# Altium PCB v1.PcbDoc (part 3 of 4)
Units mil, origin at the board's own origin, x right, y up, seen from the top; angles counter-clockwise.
Board outline 3043 x 5109 mil, 2 copper layers (Top Layer, Bottom Layer), stack 62 mil thick; 379 components, 219 nets, 963 pads, 1099 vias.
Unrouted connection lines stored in the file: 1.
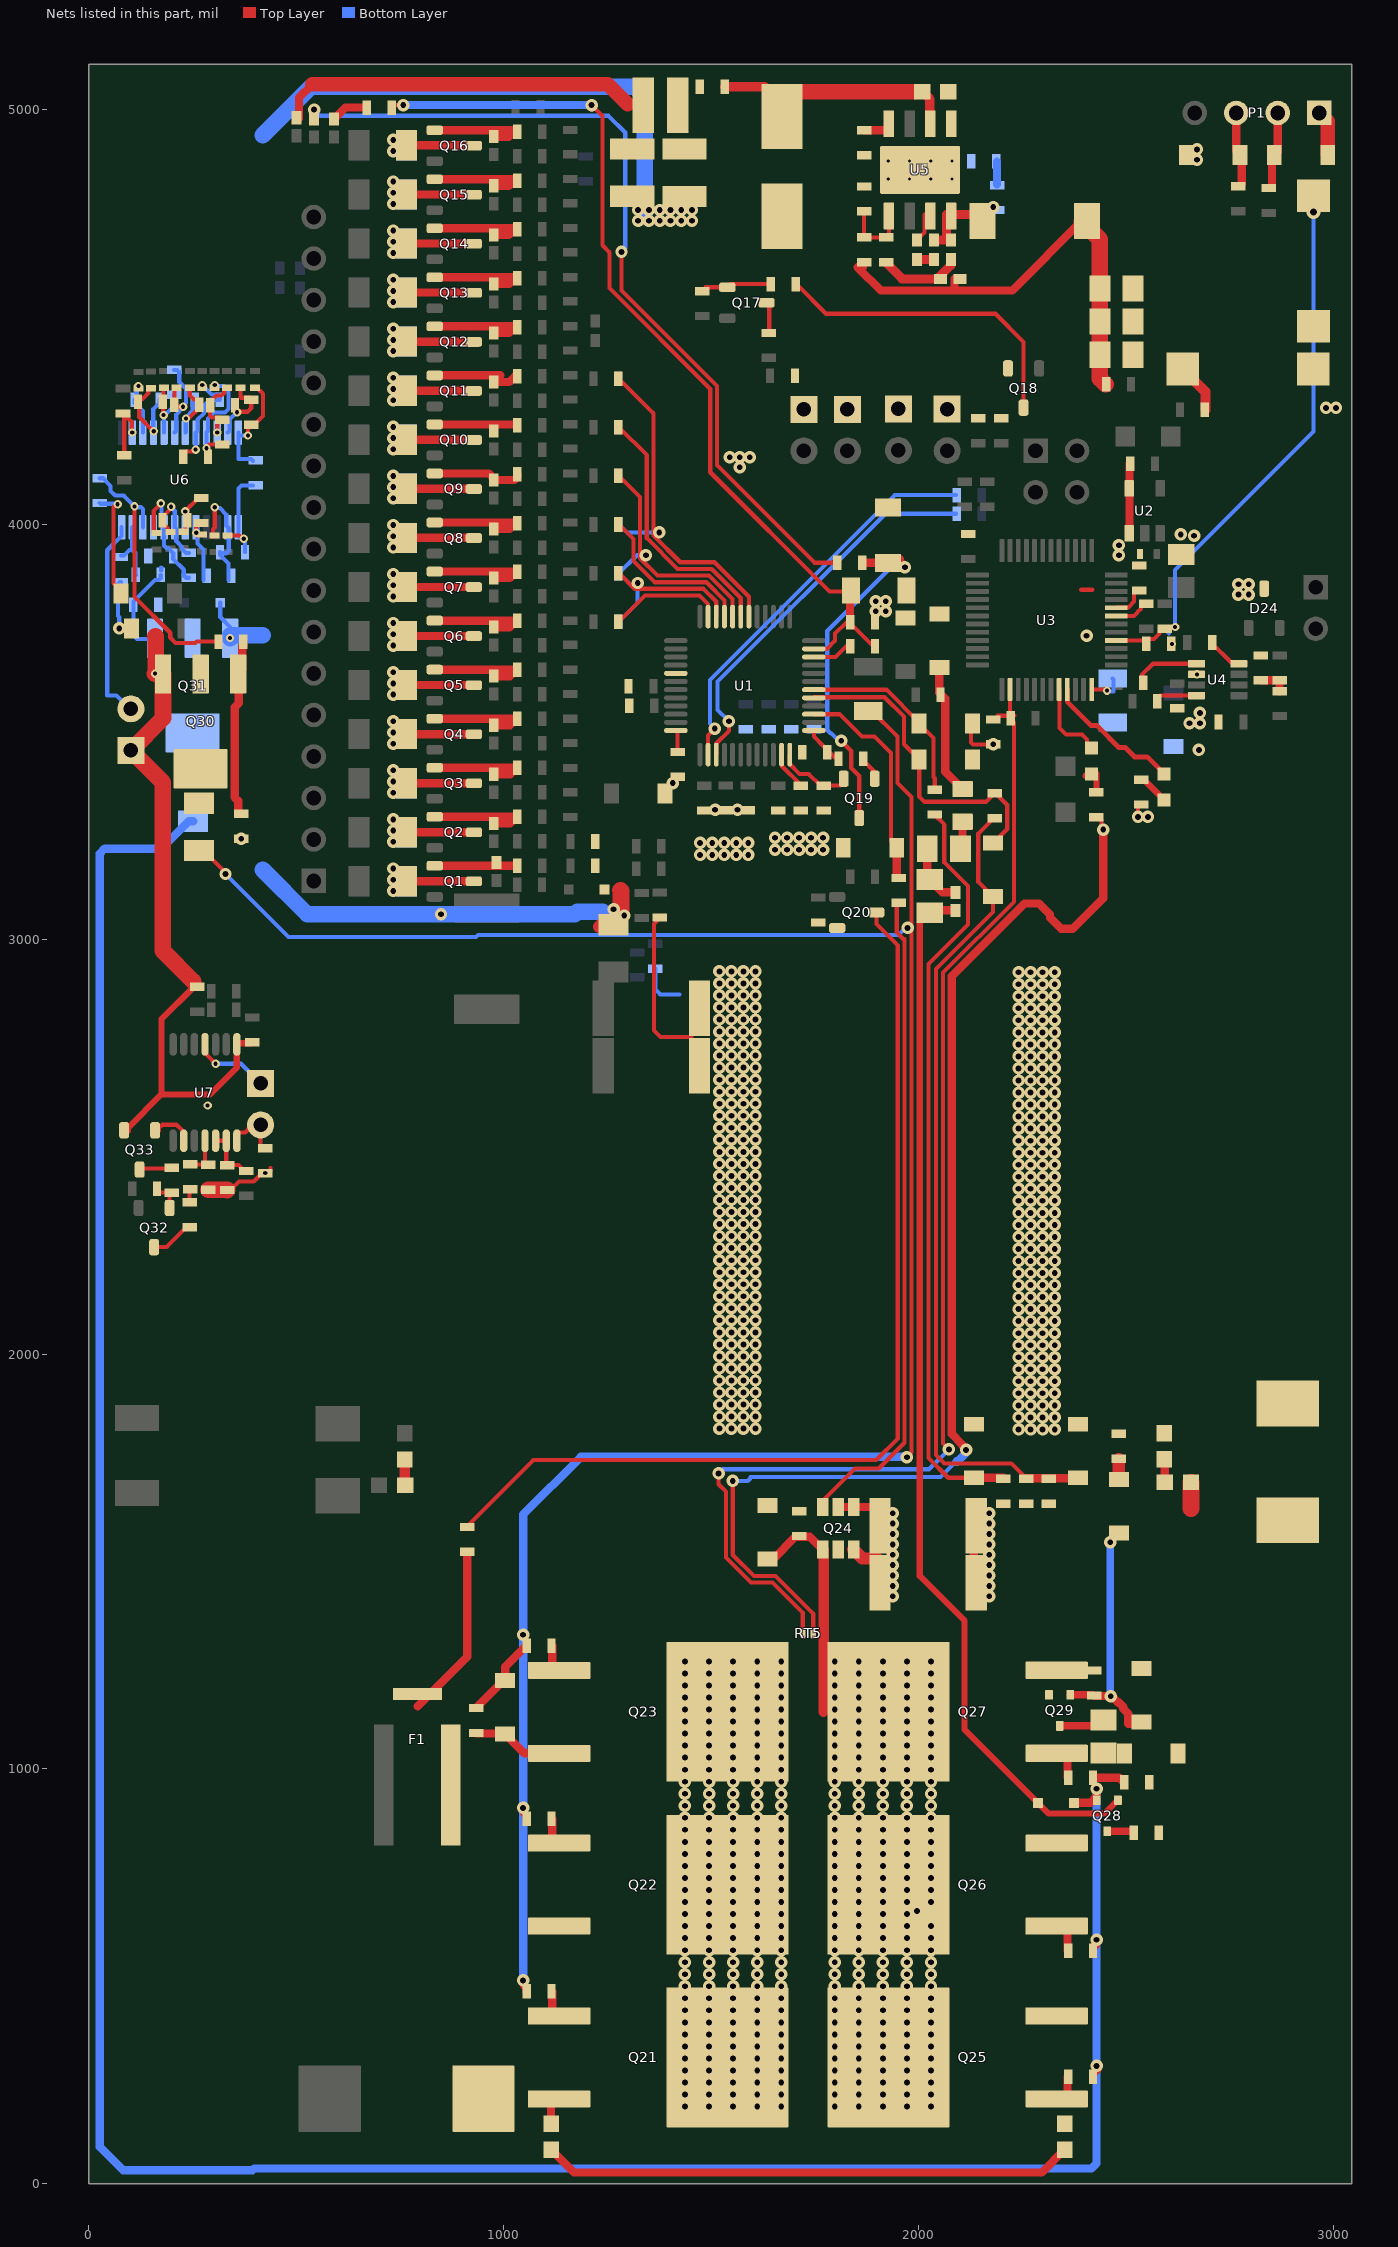
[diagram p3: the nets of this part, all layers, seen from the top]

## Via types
v1: diameter 30, hole 14, Top Layer to Bottom Layer, 1049 vias
v2: diameter 20, hole 10, Top Layer to Bottom Layer, 38 vias
v3: diameter 19.68, hole 7.87, Top Layer to Bottom Layer, tented both sides, 4 vias
v4: diameter 19.68, hole 7.87, Top Layer to Bottom Layer, 4 vias
v5: diameter 34, hole 16, Top Layer to Bottom Layer, 3 vias
v6: diameter 26, hole 10, Top Layer to Bottom Layer, 1 vias

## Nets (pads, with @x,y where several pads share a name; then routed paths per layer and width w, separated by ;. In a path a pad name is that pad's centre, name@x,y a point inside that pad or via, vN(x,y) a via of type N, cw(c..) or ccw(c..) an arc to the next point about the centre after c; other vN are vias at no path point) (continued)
GND: C1.2 C9.2 C15.1 C16.1 C17.2 C19.2 C23.2 C24.2 C25.2 C26.2 C27.1 C28.1 C30.2 C31.2 C32.2 C34.2 C35.2 C36.2 C37.1 C38.2 C39.2 C40.2 C41.1 C42.2 C43.1 C44.2 C45.2 C46.1 C47.2 C48.2 C49.2 C50.2 C51.2 C55.2 C56.2 C57.2 C64.2 C81.1 C82.1 C85.2 C86.2 C87.2 D9.2 D10.2 D21.2 D22.2 D23.2 D24.3 D32.2 D34.2 D35.2 D39.2 D41.2 D47.2 P1.1 Q18.2 Q20.2 Q30.3 Q31.3 Q33.2 R85.1 R91.1 R92.1 R99.1 R109.1 R110.1 R111.1 R116.1 R120.1 R171.1 R173.2 R174.1 R175.1 R177.2 RT1.1 RT2.1 RT3.1 RT4.1 RT5.1 RT6.1 S1.2 S2.2 U1.17 U2.1 U2.5 U3.7 U4.2 U5.1 U5.9@2003,4854 U6.21 U7.8 | length 7666.5
  Top Layer w10: C86.2@333.59,2395.35 341.09,2395.35 361.41,2415.68 397.18,2415.68 417.5,2436 v2(425,2436) 432.5,2436 437.5,2441 437.5,2448.5 ; v1(1551.41,1694.35) 1551.41,1516.35 1602.41,1465.35 1654.41,1465.35 1745.72,1374.03 RT5.1@1745.72,1326.85 ; D41.2@2129.88,3519.35 2126,3515.47 2126,3474 2130.46,3469.54 v1(2179.25,3469.54) ; 2391.55,3842.03 2418.09,3842.03 ; R109.1@2428,3294 2435.5,3294 2440.5,3289 v1@2440.5,3273.39 ; U3.7@2475.95,3779.02 2518.51,3779.02 2535.91,3796.42 2535.91,3803.35 2540.91,3808.35 C43.1@2548.41,3808.35 ; v1(2528.23,3294.56) 2528.23,3319.54 2533.23,3324.54 R110.1@2535.77,3324.54
  Top Layer w15: Q33.2@94.19,2537.6 94.19,2545.47 174.54,2625.83 ; C81.1@253.09,2885.35 174.54,2806.81 174.54,2625.83 ; C82.1@401.09,2751.35 C82.1@393.59,2751.35 391.16,2748.92 357.61,2748.92 356.36,2747.67 U7.8@356.36,2746.49 356.36,2690.36 291.83,2625.83 174.54,2625.83
  Top Layer w20: v1@2113,1770 2113,1772.71 2103.41,1782.3 2103.41,1783.19 2079.41,1807.19 2079.41,2910.65 2254.76,3086 2290,3086 2316.28,3059.72 2316.28,3051.63 2342.57,3025.35 2371.35,3025.35 2444.46,3098.46 v1(2444.46,3264.02) ; U2.1@2507.91,3979.12 C42.2@2507.91,4146.35
  Top Layer w30: R111.1@1229.91,3030.35 R111.1@1236.41,3036.84
  Top Layer w35: P1.1@2965.11,4991.3 2985.58,4970.83 D22.2@2985.58,4890.3
  Top Layer w40: v2(159,3640) 177.62,3640 Q30.3@178.45,3639.17 178.45,3532.45 RT6.1@101,3455 178.04,3377.96 178.04,2971.62 251,2898.66 ; 160.05,3730.48 161.09,3729.43 Q30.3@161.09,3650.37 ; R171.1@287.59,2396.35 332.59,2396.35 C86.2@333.59,2395.35 ; 1281,3118 1282.35,3116.65 1282.35,3071.06
  Bottom Layer w10: D47.2@316.31,3811 316.31,3776.66 340.24,3752.73 Q31.3@340.24,3731.69 ; v1(1551.41,1694.35) 1587.65,1694.35 1594,1700.69 1594,1703.35 2052.41,1703.35 2090.91,1741.85 ; 2592.41,3748.35 2596.69,3744.06 2596.69,3743.41 2602.84,3737.26
  Bottom Layer w20: 2090.91,1741.85 2094,1741.85 2114,1761.85 v1(2114,1769) v1@2113,1770
  Bottom Layer w40: Q31.3@340.24,3725.17 340.24,3731.69 340.55,3732 419,3732 ; 419,3166.93 525.93,3060 1170.77,3060 1177.11,3066.35 1238.41,3066.35 ; 419,4937.94 535.41,5054.35 1316.41,5054.35 1339.41,5031.35 v1@1339.41,4749.35
  other v1: 1290,3057 848.35,3060 1264.23,3072.27 1473,3203 1502,3203 1531,3203 1560,3203 1589,3203 1653.41,3215.35 1682.41,3215.35 1711.41,3215.35 1740.41,3215.35 1769.41,3215.35 1473,3232 1502,3232 1531,3232 1560,3232 1589,3232 367,3242 1653.41,3244.35 1682.41,3244.35 1711.41,3244.35 1740.41,3244.35 1769.41,3244.35 2552.23,3294.56 1509,3312 1563,3312 1407,3376 2675,3456 2652.41,3520.35 2677.41,3520.35 2677.41,3545.35 2404.41,3731.35 1896.41,3790.35 1920.41,3790.35 1896.41,3814.35 1920.41,3814.35 2770.41,3830.35 2795.41,3830.35 2770.41,3855.35 2795.41,3855.35 2482.41,3925.35 2482.41,3949.35 2663.41,3972.35 2631.41,3975.35 1568.41,4137.35 1544.41,4161.35 1568.41,4161.35 1592.41,4161.35 2981.41,4280.35 3005.41,4280.35 1323.41,4731.35 1349.41,4731.35 1375.41,4731.35 1401.41,4731.35 1427.41,4731.35 1453.41,4731.35 1323.41,4757.35 1349.41,4757.35 1375.41,4757.35 1401.41,4757.35 1427.41,4757.35 1453.41,4757.35 2670.41,4878.35 2670.41,4903.35
  other v2: 286,2599 2670.58,3638.14 2609.84,3711.42 339.82,3725.59
  other v3: 1926.23,4832.35 2079.77,4832.35 1926.23,4875.65 2079.77,4875.65
  other v4: 1977.41,4832.35 2028.59,4832.35 1977.41,4875.65 2028.59,4875.65
LD: D39.1 D42.2 R139.1 U1.41 | length 789.7
  Top Layer w10: U1.41@1747.09,3581.55 1747.09,3582.85 1917.91,3582.85 1964.62,3536.13 1964.62,3469.67 D39.1@2000.94,3433.35 2000.94,3343.81 2013.72,3331.03 2161.6,3331.03 2183.41,3352.84 2213.11,3323.14 2213.11,3265.61 D42.2@2179.32,3231.81
LED1: D25.2 U3.44 | length 195.4
  Top Layer w10: U3.44@2338.15,3601.85 2339.06,3600.95 2339.06,3508.7 2354.91,3492.84 2393.41,3492.84 2404.93,3481.32 2404.93,3471.86 D25.2@2415.68,3461.12
LED2: D26.2 U3.45 | length 335.2
  Top Layer w12: U3.45@2357.84,3601.85 2357.93,3601.76 2357.93,3572.15 2415.49,3514.59 2429.69,3514.59 2482.21,3462.07 2497.14,3462.07 2519.87,3439.35 2550.4,3439.35 D26.2@2591.41,3398.34
NetC15_2: C15.2 C16.2 C18.2 R61.2 U1.47 | length 2214.9
  Top Layer w10: R61.2@729.41,5004.35 729.41,5005.35 734.41,5010.35 v1(757.41,5010.35) ; v1(1211.41,5010.35) 1237.41,4984.35 1237.41,4672.35 1254.41,4655.35 1254.41,4569.35 1497.41,4326.35 1497.41,4125.35 1784.98,3837.78 C15.2@1833.91,3837.78 ; U1.47@1747.09,3699.66 1778.72,3699.66 1798.41,3719.35 1798.41,3736.35 1825.41,3763.35 1832.91,3763.35 C18.2@1889.91,3706.35 ; C16.2@1833.91,3774.35 C16.2@1836.41,3774.35
  Top Layer w20: C16.2@1833.91,3774.35 C15.2@1833.91,3837.78
  Bottom Layer w20: v1(757.41,5010.35) 1206.41,5010.35 v1@1211.41,5005.35
NetC18_1: C18.1 U1.46 | length 89.2
  Top Layer w10: U1.46@1747.09,3679.98 1799.04,3679.98 C18.1@1825.41,3706.35
NetC19_1: C19.1 U1.24 | length 52
  Top Layer w10: U1.24@1414.41,3502.81 1418.75,3498.47 C19.1@1418.75,3452.57
NetC31_1: C31.1 U1.35 | length 92.5
  Top Layer w10: U1.35@1669.33,3444.74 1669.33,3417.88 1715.64,3371.57 C31.1@1715.75,3371.57
NetC34_1: C34.1 Q19.2 U1.36 | length 185.3
  Top Layer w10: U1.36@1689.02,3444.74 1689.02,3422.1 1712.7,3398.42 1734.57,3398.42 1762.91,3370.08 C34.1@1770.41,3370.08 1809.88,3370.08 1819.01,3379.21 Q19.2@1819.01,3386.59
NetC36_1: C36.1 Q19.3 R96.1 | length 856
  Top Layer w10: v1(1813,3478) 1837.22,3453.78 1837.22,3412.09 1856.41,3392.9 Q19.3@1856.41,3292.1
  Top Layer w20: R96.1@1864.91,3907.35 1924.48,3907.35 C36.1@1925.41,3906.42 1935.12,3916.13 1954.69,3916.13 1954.69,3910.77 1966.41,3899.05 v1(1966.41,3896.35)
  Bottom Layer w10: v1(1813,3478) 1807.59,3478 1789.62,3495.97 1787.79,3495.97 1779.41,3504.35 1779.41,3742.35 1933.41,3896.35 v1(1966.41,3896.35)
NetC38_1: C38.1 R98.1 S2.1 U3.4 | length 1307.2
  Top Layer w10: U3.4@2475.95,3719.96 2543.48,3719.96 C38.1@2548.48,3714.96 ; C38.1@2548.48,3711.42 C38.1@2548.48,3714.96 ; v2(2617.69,3752.11) 2615.81,3750.23 2594.29,3750.23 R98.1@2592.41,3748.35 2584.91,3748.35 2579.91,3743.35 2579.91,3736.79 2566.54,3723.42 2553.48,3723.42 2548.48,3718.42 C38.1@2548.48,3714.96
  Bottom Layer w10: v2(2617.69,3752.11) 2617.69,3889.86 2951.41,4223.58 v5(2951.41,4752.46)
NetC39_1: C39.1 R97.1 RT5.2 U3.38 | length 3029.5
  Top Layer w10: v1(1517.41,1712.35) 1517.41,1686.35 1535.41,1668.35 1535.41,1509.72 1595.78,1449.35 1647.78,1449.35 1720.13,1376.99 RT5.2@1720.13,1326.85 ; v1(2072.41,1770.35) 2058.41,1784.35 2058.41,2919.35 2229.11,3090.05 2229.11,3522.68 R97.1@2219.75,3532.04 ; C39.1@2189.41,3537.35 2189.41,3538.34 2228.91,3538.34 2229.91,3539.35 2220.04,3549.22 U3.38@2220.04,3601.85
  Bottom Layer w10: v1(1517.41,1712.35) 1527.41,1722.35 2024.41,1722.35 v1(2072.41,1770.35)
NetC40_1: C40.1 U3.48 | length 80.9
  Top Layer w10: U3.48@2416.89,3601.85 v2@2449.15,3601.85
  Bottom Layer w10: v2(2453.35,3599) 2455.27,3597.09 2469.14,3597.09 2469.14,3626.16 C40.1@2467,3628.3
NetC46_2: C46.2 R105.1 R106.2 | length 71
  Top Layer w20: C46.2@2824.41,3623.68 R106.2@2869.41,3623.68 R105.1@2869.41,3597.68
NetC47_1: C47.1 D29.1 L1.1 | length 876.5
  Top Layer w20: D29.1@506.41,4977 506.41,5028.35 538.41,5060.35
  Top Layer w35: 538.41,5060.35 1250.41,5060.35 1298.41,5012.35
NetC48_1: C48.1 L1.2 R115.1
NetC49_1: C49.1 C50.1 R115.2 U5.2 | length 593.7
  Top Layer w23: R115.2@1532,5054 1628.77,5054 1670.41,5012.36 C50.1@1670.41,4982.84 ; C49.1@2007.91,5042.35 2008.9,5042.35 2026.7,5024.54 2026.7,4966.52 U5.2@2028,4965.22
  Top Layer w37: C50.1@1668.41,5042.35 C49.1@1990.91,5042.35
NetC51_1: C51.1 R118.1 | length 55
  Bottom Layer w20: R118.1@2188.41,4818.84 C51.1@2188.41,4873.84
NetC52_1: C52.1 R117.2 | length 41
  Top Layer w22: R117.2@1995.41,4637.72 C52.1@2036.41,4637.72
NetC52_2: C52.2 L2.1 R118.2 R119.1 U5.8 | length 177.9
  Top Layer w22: C52.2@2036.41,4684.97 2066.41,4684.97 R119.1@2077.41,4684.97 2066.41,4695.97 2066.41,4746.06 2127.41,4746.06 L2.1@2137.71,4746.06
  other v1: 2179.41,4764.35
NetC53_1: C53.1 C54.2 R119.2 | length 199
  Top Layer w22: C53.1@1921.41,4629.85 1959.91,4591.35 2044.41,4591.35 2077.41,4624.35 R119.2@2077.41,4637.72
NetC53_2: C53.2 R120.2 R121.1 U5.5 | length 171
  Top Layer w10: R120.2@1868,4754 1868,4691.69 R121.1@1868.34,4691.35 C53.2@1921.41,4691.35 1923,4691.35 1928,4696.35 U5.5@1928,4742.78
NetC54_1: C54.1 C55.1 C56.1 C57.1 L2.2 R121.2 R122.2 | length 1087.3
  Top Layer w20: 1852.41,4619.35 1908.41,4563.35 2086.03,4563.35 2225.39,4563.35 L2.2@2392.39,4730.35 ; 1865.41,4619.35 R121.2@1865.41,4629.85 ; 2086.03,4563.72 C54.1@2086.03,4591.35
  Top Layer w40: L2.2@2392.39,4730.35 2436.41,4686.33 C57.1@2436.41,4568.35 C55.1@2436.41,4488.35 C56.1@2436.41,4408.35 2436.41,4350.85 R122.2@2449.91,4337.35
NetC58_1: C58.1 C59.2 | length 62.5
  Top Layer w25: C59.2@761.41,1683.35 C58.1@761.41,1745.85
NetC60_1: C60.1 C61.2 | length 1283.4
  Top Layer w20: C60.1@1113.75,82.36 1168.76,27.35 2296.6,27.35 C61.2@2351.61,82.36
NetC60_2: C60.2 D31.2 F1.1 F2.1 Q21.3 Q22.3 Q23.3 R125.2 | length 306.5
  Top Layer w20: R125.2@933.93,1085.36 D31.2@1001.96,1085.36 ; D31.2@1002.93,1084.39 1049.57,1037.74 1105.93,1037.74 Q23.3@1162.71,1037.74 ; C60.2@1113.75,145.35 Q21.3@1113.75,204.74
NetC62_1: C62.1 C63.2 | length 55
  Top Layer w20: C63.2@2592.91,1691.35 C62.1@2592.91,1746.37
NetC64_1: C64.1 C65.2 R144.2 U6.20 | length 298.7
  Top Layer w10: R144.2@163,3979 158.5,3979 156,3981.5 156,4032.27 173.24,4049.51 v2(173.24,4050.38)
  Bottom Layer w10: v2(173.24,4050.38) 175.16,4048.47 175.16,4025.76 177.19,4023.73 177.19,3996.51 U6.20@181.05,3992.65 181.05,3948.13 186.91,3942.27 191.67,3942.27 203,3930.94 C64.1@203,3923.44 203,3915.94 228.5,3890.44 228.5,3876 233.5,3871 C65.2@241,3871
NetC65_1: C65.1 C66.2 R145.2 U6.19 | length 208.4
  Top Layer w10: R145.2@197,3981 192.5,3981 190,3983.5 190,3989.5 177,4002.5 C66.2@177,4010 177,4017.5 196.09,4036.59 196.09,4040.09 v2(198,4042)
  Bottom Layer w10: v2(198,4042) 198,4040.16 206.64,4031.52 U6.19@206.64,3992.65 ; U6.19@210.5,3988.8 210.5,3959 224,3945.5 224,3940.5 233.5,3931 C65.1@241,3931
NetC66_1: C66.1 C67.2 R146.2 U6.18 | length 147
  Top Layer w10: R146.2@228,3982 230,3982 232.5,3984.5 232.5,4005.5 C66.1@237,4010 233.91,4013.09 233.91,4029.09 v2(232,4031) 232,4031.5 263.5,4063 C67.2@271,4063
  Bottom Layer w10: v2(232,4031) 232.11,4030.89 232.11,3992.77 U6.18@232.23,3992.65
NetC67_1: C67.1 C68.2 R147.2 U6.17 | length 190.6
  Top Layer w10: R147.2@262,3972 260.25,3973.75 260.25,3977.81 v2(258.5,3979.56) 258.5,3998 263.5,4003 C67.1@271,4003
  Bottom Layer w10: v2(258.5,3979.56) 258.5,3991.97 U6.17@257.82,3992.65 261.68,3988.8 261.68,3953.38 276,3939.06 C68.2@276,3865
NetC68_1: C68.1 C69.2 R148.2 U6.14 | length 299.7
  Top Layer w10: R148.2@296.5,3970 299,3972.5 299,3987.94 303,3991.94 v2(303,4041)
  Bottom Layer w10: v2(303,4041) 304.91,4039.09 315.37,4039.09 330.73,4023.72 330.73,3996.51 U6.14@334.59,3992.65 336.78,3990.46 336.78,3935.86 330.92,3930 319,3930 C69.2@316,3933 316,3925.5 336,3905.5 C68.1@336,3865
NetC69_1: C69.1 C70.2 R149.2 U6.13 | length 229.1
  Top Layer w10: R149.2@333.69,3973 362.56,3973 370.37,3965.2 v2(373.07,3965.2)
  Bottom Layer w10: U6.13@364.04,3968.13 360.18,3971.98 U6.13@360.18,3992.65 360.18,4086 367.18,4093 C70.2@395,4093 ; C69.1@376,3933 v2@376,3962.27
NetC70_1: C70.1 C71.2 R150.2 U6.12 | length 275.2
  Top Layer w10: v2(383,4214) 383,4235 388,4240 C71.2@391,4240 398.5,4240 419.5,4261 419.5,4314.56 413.06,4321 412.5,4321 404.5,4329 R150.2@400,4329
  Bottom Layer w10: v2(383,4214) 364.04,4214 360.18,4217.86 U6.12@360.18,4221 360.18,4214 360.18,4157.18 390.82,4157.18 C70.1@395,4153
NetC71_1: C71.1 C72.2 R151.2 U6.11 | length 187.5
  Top Layer w10: C72.2@352,4287 357,4282 v2(357,4270) 358,4271 382,4271 391,4280 C71.1@391,4300 C71.1@383.5,4300 ; R151.2@365,4329 365,4306.5 366.5,4305 C71.1@386,4305
  Bottom Layer w10: U6.11@334.59,4221 338.45,4224.86 338.45,4252.07 356.38,4270 v2(357,4270)
NetC72_1: C72.1 C73.2 R152.2 U6.10 | length 160.2
  Top Layer w10: v2(309,4221) 309,4247 314,4252 316,4252 C73.2@321,4252 ; C73.2@316,4257 314,4257 295.86,4257 292,4260.86 C72.1@292,4287 292,4294.5 307.37,4309.87 318.93,4309.87 326,4316.94 326,4326.5 328.5,4329 R152.2@333,4329
NetC73_1: C73.1 C74.2 R153.2 U6.9 | length 280.3
  Top Layer w10: C74.2@287,4163 284.91,4165.09 284.91,4181.09 v2(283,4183) 283,4185.71 288.86,4191.56 288.86,4192 C73.1@321,4192
  Bottom Layer w10: v2(283,4183) 283.2,4183.2 283.2,4220.8 287.27,4224.86 287.27,4255.03 292.92,4260.69 292.92,4261.46 301.17,4269.7 327.76,4269.7 336,4277.94 336,4322.06 324.75,4333.31 304.91,4333.31 v2(303,4335.22)
NetC74_1: C74.1 C75.2 R154.2 U6.8 | length 260.4
  Top Layer w10: C74.1@227,4163 227,4170.5 232,4175.5 250.06,4175.5 254.29,4179.73 v2(257,4179.73)
  Bottom Layer w10: v2(257,4179.73) 257.41,4180.14 257.41,4220.59 U6.8@257.82,4221 261.68,4224.86 261.68,4252.07 276.92,4267.31 276.92,4285.51 291.42,4300 C75.2@315,4300 315,4307.5 310,4312.5 295.72,4312.5 v2(273,4335.22)
NetC75_1: C75.1 C76.2 R155.2 U6.7 | length 193.3
  Top Layer w10: v2(234,4255) 235.91,4256.91 242.52,4256.91 265.84,4280.23 C76.2@265.84,4287.73 265.84,4295.23 260.84,4300.23 253.34,4300.23 243,4310.57 R155.2@243,4329
  Bottom Layer w10: U6.7@232.23,4221 233.11,4221.89 233.11,4254.11 v2(234,4255) 234,4257.71 250,4273.71 250,4295 C75.1@255,4300
NetC76_1: C76.1 C77.2 R156.2 U6.6 | length 246.3
  Top Layer w10: R156.2@211,4329 208.34,4329 205.84,4326.5 C76.1@205.84,4287.73 210.31,4283.27 v2(227,4283.27)
  Bottom Layer w10: C77.2@205,4372 212.5,4372 217.5,4367 217.5,4342.56 233.5,4326.56 233.5,4292.47 227,4285.97 v2(227,4283.27) 227,4280.92 210.5,4264.42 210.5,4224.86 U6.6@206.64,4221
NetC77_1: C77.1 C78.2 R157.2 U6.5 | length 170.8
  Top Layer w10: C78.2@179.92,4294 179.92,4327.92 R157.2@181,4329 ; v2(180,4263) 179,4264 179,4293 C78.2@180,4294
  Bottom Layer w10: U6.5@181.05,4221 180.52,4221.52 180.52,4262.48 v2(180,4263) 182.71,4263 197.63,4277.93 197.93,4277.93 205,4285 C77.1@205,4312
NetC78_1: C78.1 C79.2 R158.2 U6.4 | length 219.6
  Top Layer w10: R158.2@150,4328 145.5,4328 143,4325.5 143,4315.94 127.29,4300.23 123.84,4300.23 118.84,4295.23 121.21,4292.87 121.21,4258.79 v2(156,4224)
  Bottom Layer w10: v2(156,4224) 155,4225 155,4277.5 170,4292.5 C79.2@170,4300
NetC79_1: C79.1 R159.2 U6.3 | length 124.2
  Bottom Layer w10: v2(119,4333.22) 119,4330.51 115,4326.51 115,4305 C79.1@110,4300 110,4292.5 129.87,4272.63 U6.3@129.87,4221
NetC80_1: C80.1 R160.1 U6.2 | length 161.9
  Top Layer w10: C80.1@85,4166 85,4264 R160.1@82,4267 89.5,4267 94.5,4262 94.5,4254.5 103,4246 103,4222.28 v2(104.28,4221)
NetC85_1: C85.1 RT7.2 U7.7 | length 147.6
  Top Layer w10: U7.7@356.36,2514.21 356.36,2530.82 359.92,2534.39 376.54,2534.39 383.98,2541.83 403.06,2541.83 RT7.2@413.59,2552.35 413.59,2501 418.59,2496 C85.1@425,2496
NetC86_1: C86.1 R172.2 U7.5 U7.6 | length 138.3
  Top Layer w10: U7.5@305.18,2514.21 U7.6@330.77,2514.21 330.77,2458.17 C86.1@333.59,2455.35 360.23,2455.35 366.09,2449.49 366.09,2446.35 371.09,2441.35 R172.2@378.59,2441.35
NetD1_1: D1.1 Q1.1 R18.1 | length 198
  Top Layer w20: Q1.1@833.17,3176.75 1030.35,3176.75 R18.1@1030.91,3177.31
NetD2_1: D2.1 Q2.1 R20.1 | length 259.2
  Top Layer w20: Q2.1@833.17,3294.95 1030.61,3294.95 1014.86,3279.2 D2.1@975.41,3279.2
NetD3_1: D3.1 Q3.1 R22.1 | length 259.7
  Top Layer w20: Q3.1@833.17,3413.15 1030.88,3413.15 1015.13,3397.4 D3.1@975.41,3397.4
NetD4_1: D4.1 Q4.1 R24.1 | length 259.3
  Top Layer w20: Q4.1@833.17,3531.35 1030.69,3531.35 1014.94,3515.6 D4.1@975.41,3515.6
NetD5_1: D5.1 Q5.1 R26.1 | length 258.8
  Top Layer w20: Q5.1@833.17,3649.55 1030.42,3649.55 1014.67,3633.8 D5.1@975.41,3633.8
NetD6_1: D6.1 Q6.1 R28.1 | length 258.3
  Top Layer w20: Q6.1@833.17,3767.75 1030.16,3767.75 1014.41,3752 D6.1@975.41,3752
NetD7_1: D7.1 Q7.1 R30.1 | length 257.7
  Top Layer w20: Q7.1@833.17,3885.95 1029.89,3885.95 1014.14,3870.2 D7.1@975.41,3870.2
NetD8_1: D8.1 Q8.1 R32.1 | length 257.2
  Top Layer w20: Q8.1@833.17,4004.15 1029.63,4004.15 1013.88,3988.4 D8.1@975.41,3988.4
NetD11_1: D11.1 R61.1 | length 88.8
  Top Layer w20: D11.1@590.41,4977 617.76,5004.35 R61.1@667.91,5004.35
NetD12_1: D12.1 Q9.1 R51.1 | length 218.3
  Top Layer w20: Q9.1@833.17,4122.35 963.6,4122.35 975.41,4110.54 D12.1@975.41,4106.6 1025.71,4106.6 1032.41,4113.3 R51.1@1032.41,4120.8
NetD13_1: D13.1 Q10.1 R53.1 | length 211.9
  Top Layer w20: Q10.1@833.17,4240.55 976,4240.55 ; D13.1@975.41,4224.8 976,4225.39 976,4240.55 ; R53.1@1029.1,4240.55 976,4240.55
NetD14_1: D14.1 Q11.1 R55.1 | length 227.4
  Top Layer w20: Q11.1@833.17,4358.75 991.16,4358.75 ; D14.1@977.22,4348.75 975.41,4346.94 D14.1@975.41,4343 1013.09,4343 1028.83,4358.75 R55.1@1030.91,4356.67
NetD15_1: D15.1 Q12.1 R57.1 | length 255.1
  Top Layer w20: Q12.1@833.17,4476.95 1028.57,4476.95 1012.82,4461.2 D15.1@975.41,4461.2
NetD16_1: D16.1 Q13.1 R59.1 | length 254.6
  Top Layer w20: Q13.1@833.17,4595.15 1028.3,4595.15 1012.56,4579.4 D16.1@975.41,4579.4
NetD17_1: D17.1 Q14.1 R79.1 | length 254
  Top Layer w20: Q14.1@833.17,4713.35 1028.04,4713.35 1012.29,4697.6 D17.1@975.41,4697.6
NetD18_1: D18.1 Q15.1 R81.1 | length 253.5
  Top Layer w20: Q15.1@833.17,4831.55 1027.78,4831.55 1012.03,4815.8 D18.1@975.41,4815.8
NetD19_1: D19.1 Q16.1 R83.1 | length 253
  Top Layer w20: Q16.1@833.17,4949.75 1027.51,4949.75 1011.76,4934 D19.1@975.41,4934
NetD20_1: D20.1 R96.2 | length 2082
  Top Layer w10: D20.1@542.41,4977 v1(542.41,4999.35) ; v1(1283.41,4656.35) 1283.41,4562.97 1513.41,4332.97 1513.41,4142.35 1748.41,3907.35 R96.2@1801.91,3907.35
  Bottom Layer w10: v1(542.41,4999.35) 557.41,4984.35 1252.41,4984.35 1292.41,4944.35 1292.41,4665.35 v1(1283.41,4656.35)
NetD22_1: D22.1 P1.2 R107.2 | length 177.7
  Top Layer w20: R107.2@2851.11,4819.03 2851.11,4884.76 D22.1@2856.64,4890.3 D22.1@2864.11,4897.76 ; D22.1@2865.11,4897.76 P1.2@2865.11,4991.3
NetD23_1: D23.1 P1.3 R108.2 | length 172.7
  Top Layer w20: D23.1@2765.11,4899.76 P1.3@2765.11,4991.3 ; D23.1@2773.58,4890.3 2778.11,4894.83 R108.2@2778.11,4820.09
NetD25_1: D25.1 R109.2 | length 72.8
  Top Layer w15: D25.1@2401.46,3393.31 2407.23,3399.08 2428.23,3399.08 2428.23,3355.73 R109.2@2428,3355.5
NetD26_1: D26.1 R110.2 | length 76.6
  Top Layer w15: R110.2@2535.77,3386.04 2540.72,3386.04 D26.1@2591.41,3335.35
NetD31_1: D31.1 L3.1 L4.1 L5.1 R124.2 R125.1 R163.2 | length 6017
  Top Layer w10: R163.2@265.05,3213.39 275.87,3213.39 329,3160.27 v1(329,3157) ; R124.2@1878.41,3550.2 1886.56,3550.2 1948.62,3488.13 1948.62,3376.35 1982.41,3342.56 1982.41,1762.35 v1(1971.41,1751.35)
  Top Layer w20: R125.1@933.93,1148.35 D31.1@998.9,1213.32 ; D31.1@1002.93,1213.32 1002.93,1246.35 L5.1@1053.43,1296.85 ; v1(1046.41,490.35) 1048.32,488.43 1048.32,477.96 1054.93,471.35 L3.1@1054.93,463.85 ; v1(1046.41,906.35) 1048.32,904.43 1048.32,894.46 1054.93,887.85 L4.1@1054.93,880.35
  Bottom Layer w10: v1(329,3157) 481,3005 933.03,3005 938.03,3010 1950.59,3010 1967.59,3027 v1(1973,3027)
  Bottom Layer w20: v1(1046.41,490.35) v1(1046.41,906.35) v1(1046.41,1323.35) 1046.41,1613.35 1185.41,1752.35 v1@1970.41,1752.35
NetD33_1: D33.1 Q21.2 Q22.2 Q23.2 Q24.4 Q25.2 Q26.2 Q27.2 R127.2 | length 759
  Top Layer w20: D33.1@1634.89,1506.35 1649.42,1506.35 1703.06,1559.99 1711.52,1559.99 1737,1559.99 Q24.4@1768.01,1528.98
  Top Layer w25: Q24.4@1768.01,1528.98 1771.11,1528.98 1771.11,1296.54 1770.41,1296.54 1770.41,1137.84
  Top Layer w30: 1774.41,1276.32 Q27.2@1912.89,1137.84
  other v1: 1436.41,186.35 1494.41,186.35 1552.41,186.35 1610.41,186.35 1668.41,186.35 1797.41,186.35 1855.41,186.35 1913.41,186.35 1971.41,186.35 2029.41,186.35 1436.41,215.35 1494.41,215.35 1552.41,215.35 1610.41,215.35 1668.41,215.35 1797.41,215.35 1855.41,215.35 1913.41,215.35 1971.41,215.35 2029.41,215.35 1436.41,244.35 1494.41,244.35 1552.41,244.35 1610.41,244.35 1668.41,244.35 1797.41,244.35 1855.41,244.35 1913.41,244.35 1971.41,244.35 2029.41,244.35 1436.41,273.35 1494.41,273.35 1552.41,273.35 1610.41,273.35 1668.41,273.35 1797.41,273.35 1855.41,273.35 1913.41,273.35 1971.41,273.35 2029.41,273.35 1436.41,302.35 1494.41,302.35 1552.41,302.35 1610.41,302.35 1668.41,302.35 1797.41,302.35 1855.41,302.35 1913.41,302.35 1971.41,302.35 2029.41,302.35 1436.41,331.35 1494.41,331.35 1552.41,331.35 1610.41,331.35 1668.41,331.35 1797.41,331.35 1855.41,331.35 1913.41,331.35 1971.41,331.35 2029.41,331.35 1436.41,360.35 1494.41,360.35 1552.41,360.35 1610.41,360.35 1668.41,360.35 1797.41,360.35 1855.41,360.35 1913.41,360.35 1971.41,360.35 2029.41,360.35 1436.41,389.35 1494.41,389.35 1552.41,389.35 1610.41,389.35 1668.41,389.35 1797.41,389.35 1855.41,389.35 1913.41,389.35 1971.41,389.35 2029.41,389.35 1436.41,418.35 1494.41,418.35 1552.41,418.35 1610.41,418.35 1668.41,418.35 1797.41,418.35 1855.41,418.35 1913.41,418.35 1971.41,418.35 2029.41,418.35 1436.41,447.35 1494.41,447.35 1552.41,447.35 1610.41,447.35 1668.41,447.35 1797.41,447.35 1855.41,447.35 1913.41,447.35 1971.41,447.35 2029.41,447.35 1436.41,476.35 1494.41,476.35 1552.41,476.35 1610.41,476.35 1668.41,476.35 1797.41,476.35 1855.41,476.35 1913.41,476.35 1971.41,476.35 2029.41,476.35 1436.41,505.35 1494.41,505.35 1552.41,505.35 1610.41,505.35 1668.41,505.35 1797.41,505.35 1855.41,505.35 1913.41,505.35 1971.41,505.35 2029.41,505.35 1436.41,534.35 1494.41,534.35 1552.41,534.35 1610.41,534.35 1668.41,534.35 1797.41,534.35 1855.41,534.35 1913.41,534.35 1971.41,534.35 2029.41,534.35 1436.41,563.35 1494.41,563.35 1552.41,563.35 1610.41,563.35 1668.41,563.35 1797.41,563.35 1855.41,563.35 1913.41,563.35 1971.41,563.35 2029.41,563.35 1436.41,592.35 1494.41,592.35 1552.41,592.35 1610.41,592.35 1668.41,592.35 1797.41,592.35 1855.41,592.35 1913.41,592.35 1971.41,592.35 2029.41,592.35 1436.41,621.35 1494.41,621.35 1552.41,621.35 1610.41,621.35 1668.41,621.35 1797.41,621.35 1855.41,621.35 1913.41,621.35 1971.41,621.35 2029.41,621.35 1436.41,650.35 1494.41,650.35 1552.41,650.35 1610.41,650.35 1668.41,650.35 1797.41,650.35 1855.41,650.35 1913.41,650.35 1971.41,650.35 1995.26,657.37 1436.41,679.35 1494.41,679.35 1552.41,679.35 1610.41,679.35 1668.41,679.35 1797.41,679.35 1855.41,679.35 1913.41,679.35 1971.41,679.35 2029.41,679.35 1436.41,708.35 1494.41,708.35 1552.41,708.35 1610.41,708.35 1668.41,708.35 1797.41,708.35 1855.41,708.35 1913.41,708.35 1971.41,708.35 2029.41,708.35 1436.41,737.35 1494.41,737.35 1552.41,737.35 1610.41,737.35 1668.41,737.35 1797.41,737.35 1855.41,737.35 1913.41,737.35 1971.41,737.35 2029.41,737.35 1436.41,766.35 1494.41,766.35 1552.41,766.35 1610.41,766.35 1668.41,766.35 1797.41,766.35 1855.41,766.35 1913.41,766.35 1971.41,766.35 2029.41,766.35 1436.41,795.35 1494.41,795.35 1552.41,795.35 1610.41,795.35 1668.41,795.35 1797.41,795.35 1855.41,795.35 1913.41,795.35 1971.41,795.35 2029.41,795.35 1436.41,824.35 1494.41,824.35 1552.41,824.35 1610.41,824.35 1668.41,824.35 1797.41,824.35 1855.41,824.35 1913.41,824.35 1971.41,824.35 2029.41,824.35 1436.41,853.35 1494.41,853.35 1552.41,853.35 1610.41,853.35 1668.41,853.35 1797.41,853.35 1855.41,853.35 1913.41,853.35 1971.41,853.35 2029.41,853.35 1436.41,882.35 1494.41,882.35 1552.41,882.35 1610.41,882.35 1668.41,882.35 1797.41,882.35 1855.41,882.35 1913.41,882.35 1971.41,882.35 2029.41,882.35 1436.41,911.35 1494.41,911.35 1552.41,911.35 1610.41,911.35 1668.41,911.35 1797.41,911.35 1855.41,911.35 1913.41,911.35 1971.41,911.35 2029.41,911.35 1436.41,940.35 1494.41,940.35 1552.41,940.35 1610.41,940.35 1668.41,940.35 1797.41,940.35 1855.41,940.35 1913.41,940.35 1971.41,940.35 2029.41,940.35 1436.41,969.35 1494.41,969.35 1552.41,969.35 1610.41,969.35 1668.41,969.35 1797.41,969.35 1855.41,969.35 1913.41,969.35 1971.41,969.35 2029.41,969.35 1436.41,998.35 1494.41,998.35 1552.41,998.35 1610.41,998.35 1668.41,998.35 1797.41,998.35 1855.41,998.35 1913.41,998.35 1971.41,998.35 2029.41,998.35 1436.41,1027.35 1494.41,1027.35 1552.41,1027.35 1610.41,1027.35 1668.41,1027.35 1797.41,1027.35 1855.41,1027.35 1913.41,1027.35 1971.41,1027.35 2029.41,1027.35 1436.41,1056.35 1494.41,1056.35 1552.41,1056.35 1610.41,1056.35 1668.41,1056.35 1797.41,1056.35 1855.41,1056.35 1913.41,1056.35 1971.41,1056.35 2029.41,1056.35 1436.41,1085.35 1494.41,1085.35 1552.41,1085.35 1610.41,1085.35 1668.41,1085.35 1797.41,1085.35 1855.41,1085.35 1913.41,1085.35 1971.41,1085.35 2029.41,1085.35 1436.41,1114.35 1494.41,1114.35 1552.41,1114.35 1610.41,1114.35 1668.41,1114.35 1797.41,1114.35 1855.41,1114.35 1913.41,1114.35 1971.41,1114.35 2029.41,1114.35 1436.41,1143.35 1494.41,1143.35 1552.41,1143.35 1610.41,1143.35 1668.41,1143.35 1797.41,1143.35 1855.41,1143.35 1913.41,1143.35 1971.41,1143.35 2029.41,1143.35 1436.41,1172.35 1494.41,1172.35 1552.41,1172.35 1610.41,1172.35 1668.41,1172.35 1797.41,1172.35 1855.41,1172.35 1913.41,1172.35 1971.41,1172.35 2029.41,1172.35 1436.41,1201.35 1494.41,1201.35 1552.41,1201.35 1610.41,1201.35 1668.41,1201.35 1797.41,1201.35 1855.41,1201.35 1913.41,1201.35 1971.41,1201.35 2029.41,1201.35 1436.41,1230.35 1494.41,1230.35 1552.41,1230.35 1610.41,1230.35 1668.41,1230.35 1797.41,1230.35 1855.41,1230.35 1913.41,1230.35 1971.41,1230.35 2029.41,1230.35 1436.41,1259.35 1494.41,1259.35 1552.41,1259.35 1610.41,1259.35 1668.41,1259.35 1797.41,1259.35 1855.41,1259.35 1913.41,1259.35 1971.41,1259.35 2029.41,1259.35
NetD33_2: D33.2 Q24.3 R126.2 R127.1 | length 1578.5
  Top Layer w10: Q24.3@1768.01,1631.35 1768.01,1645.95 1846.41,1724.35 1903.41,1724.35 1965.41,1786.35 1965.41,3000 ; R126.2@1951.41,3087.56 1947,3083.15 1947,3016.23 1962.23,3001
NetD35_1: D35.1 R131.2 R133.1 | length 310
  Top Layer w20: R131.2@2049.41,3593.84 D35.1@2049.41,3654.88 ; R131.2@2053.91,3589.35 2063.41,3579.84 2063.41,3403.72 R133.1@2105.41,3361.72
NetD36_1: D36.1 D37.2 Q28.1 R130.2 | length 2554
  Top Layer w15: R130.2@2026.41,3063.55 2002.41,3039.55 2002.41,1465.35 2110.41,1357.35 2110.41,1095.04 D37.2@2287.1,918.35 2312.41,893.04 2448.29,893.04 Q28.1@2480,924.75
  Top Layer w20: R130.2@2026.41,3063.55 2032.26,3069.39 D36.1@2088.41,3069.39
NetD36_2: D36.2 R130.1 R134.1 | length 151.6
  Top Layer w20: R134.1@2020.41,3217.85 2020.41,3149.55 R130.1@2026.41,3143.55 2057.25,3112.7 D36.2@2088.41,3112.7
NetD37_1: D37.1 D38.1 L6.1 L7.1 L8.1 Q28.2 R132.1 R135.1 R164.1 | length 6928.3
  Top Layer w20: D37.1@2373.72,918.35 2413.41,918.35 2428.41,933.35 v1(2428.41,952.35) ; L6.1@2419.93,257.85 2419.93,265.35 2429.97,275.4 2430.32,275.4 2430.32,282.43 v1(2428.41,284.35) ; L7.1@2419.93,561.85 2419.93,569.35 2426.5,575.92 2426.5,586.43 v1(2428.41,588.35) ; L8.1@2421.43,978.85 2483.41,978.85 R132.1@2493.91,968.35
  Bottom Layer w20: R164.1@251,3283.91 240.17,3283.91 174.26,3218 37.72,3218 26,3206.28 26,89 82,33 394,33 398,37 2416,37 2428.41,49.41 v1(2428.41,284.35) v1(2428.41,588.35) v1(2428.41,952.35)
NetD40_1: D40.1 D43.1 Q29.1 R138.2 | length 620.9
  Top Layer w18: Q29.1@2365,1178.75 R138.2@2419.51,1178.75 ; v1(2461.41,1546.35) 2463.71,1548.64 2463.71,1556.18 2476.41,1568.88 D43.1@2482.41,1568.88
  Top Layer w20: R138.2@2422.41,1175.85 2461.91,1175.85 v1(2462.41,1175.35) 2465.12,1175.35 2481.12,1159.35 2483.54,1159.35 2492.91,1149.97 2492.91,1144.85 2504.41,1133.35 2504.41,1108.88 2532.35,1108.88 D40.1@2537,1113.53
  Bottom Layer w18: v1@2461.41,1176.35 v1(2461.41,1546.35)
NetD42_1: D42.1 D45.1 R139.2 R142.1 R143.1 | length 1989
  Top Layer w10: R139.2@2183.41,3289.85 2178.86,3289.85 2143.39,3254.38 2143.39,3137.89 D42.1@2178.41,3102.88 2178.41,3065.35 2041.41,2928.35 2041.41,1756.35 2061.41,1736.35 2222.91,1736.35 R143.1@2258.41,1700.84
  Top Layer w20: R143.1@2258.41,1700.84 2313.41,1700.84 D45.1@2383.41,1700.84
NetD43_2: D43.2 R137.2 | length 48.6
  Top Layer w30: D43.2@2482.41,1697.82 R137.2@2482.41,1746.37
NetD44_1: D44.1 R140.2 R141.1 | length 1822.7
  Top Layer w10: R140.2@2038.41,3298.85 2061.41,3275.85 2061.41,3184.79 2118.41,3127.79 2118.41,3035.35 2023.41,2940.35 2023.41,1749.35 2070.88,1701.88 D44.1@2133.41,1701.88
  Top Layer w20: D44.1@2133.41,1701.88 2203.41,1701.88 R141.1@2203.41,1700.84
NetD48_2: D48.2 R178.1 | length 157.2
  Top Layer w10: v1(73,3748.78) 92.52,3748.78 105.53,3735.77 D48.2@105.53,3734
  Bottom Layer w10: v1(73,3748.78) 73,3775.78 70,3778.78 70,3856 75,3861 R178.1@77,3861
NetD49_2: D49.2 R180.1 | length 273.6
  Top Layer w10: v2(69,4048) 66.29,4048 60.44,4042.14 58.92,4042.14 58.92,3857.61 77.53,3839 D49.2@77.53,3833
  Bottom Layer w10: R180.1@26,4051 27.5,4049.5 67.5,4049.5 v2(69,4048)
NetF1_2: F1.2 R123.1 | length 419.8
  Top Layer w20: 792.41,1151.35 911.41,1270.35 R123.1@911.41,1521.85
NetL3_2: L3.2 Q21.1 | length 59.1
  Top Layer w20: Q21.1@1116.43,404.74 L3.2@1116.43,463.85
NetL4_2: L4.2 Q22.1 | length 59.1
  Top Layer w20: Q22.1@1116.43,821.24 L4.2@1116.43,880.35
NetL5_2: L5.2 Q23.1 | length 56.5
  Top Layer w20: Q23.1@1116.43,1240.36 L5.2@1116.43,1296.85
NetL6_2: L6.2 Q25.1 | length 49.5
  Top Layer w20: Q25.1@2358.43,208.32 L6.2@2358.43,257.85
NetL7_2: L7.2 Q26.1 | length 52.5
  Top Layer w20: L7.2@2358.43,561.85 Q26.1@2358.43,614.37
NetL8_2: L8.2 Q27.1 | length 90.3
  Top Layer w20: Q27.1@2302.65,1037.84 Q27.1@2333.91,1037.84 ; L8.2@2358.43,978.85 Q27.1@2358.43,1037.87
NetQ1_3: Q1.3 R1.2 R2.2 | length 162.6
  Top Layer w20: R2.2@765.03,3139.35 Q1.3@927.65,3139.35
  other v1: 733.41,3116.35 733.41,3143.35 733.41,3170.35
NetQ2_3: Q2.3 R3.2 R4.2 | length 162.6
  Top Layer w20: R4.2@765.03,3257.6 Q2.3@927.6,3257.6
  other v1: 733.41,3234.6 733.41,3261.6 733.41,3288.6
NetQ3_3: Q3.3 R5.2 R6.2 | length 162.5
  Top Layer w20: R6.2@765.03,3375.86 Q3.3@927.54,3375.86
  other v1: 733.41,3352.86 733.41,3379.86 733.41,3406.86
NetQ4_3: Q4.3 R7.2 R8.2 | length 162.5
  Top Layer w20: R8.2@765.03,3494.12 Q4.3@927.48,3494.12
  other v1: 733.41,3471.12 733.41,3498.12 733.41,3525.12
NetQ5_3: Q5.3 R9.2 R10.2 | length 162.4
  Top Layer w20: R10.2@765.03,3612.38 Q5.3@927.42,3612.38
  other v1: 733.41,3589.38 733.41,3616.38 733.41,3643.38
NetQ6_3: Q6.3 R11.2 R12.2 | length 162.3
  Top Layer w20: R12.2@765.03,3730.63 Q6.3@927.37,3730.63
  other v1: 733.41,3707.63 733.41,3734.63 733.41,3761.63
NetQ7_3: Q7.3 R13.2 R14.2 | length 162.3
  Top Layer w20: R13.2@765.03,3848.89 Q7.3@927.31,3848.89
  other v1: 733.41,3825.89 733.41,3852.89 733.41,3879.89
NetQ8_3: Q8.3 R15.2 R16.2 | length 162.2
  Top Layer w20: R16.2@765.03,3967.15 Q8.3@927.25,3967.15
  other v1: 733.41,3944.15 733.41,3971.15 733.41,3998.15
NetQ9_3: Q9.3 R36.2 R37.2 | length 162.2
  Top Layer w20: R37.2@765.03,4085.4 Q9.3@927.2,4085.4
  other v1: 733.41,4062.4 733.41,4089.4 733.41,4116.4
NetQ10_3: Q10.3 R38.2 R39.2 | length 162.1
  Top Layer w20: R39.2@765.03,4203.66 Q10.3@927.14,4203.66
  other v1: 733.41,4180.66 733.41,4207.66 733.41,4234.66
NetQ11_3: Q11.3 R40.2 R41.2 | length 195.3
  Top Layer w20: v1(733.41,4325.92) 761.03,4325.92 R41.2@765.03,4321.92 Q11.3@927.08,4321.92
  other v1: 733.41,4298.92 733.41,4352.92
NetQ12_3: Q12.3 R42.2 R43.2 | length 195.3
  Top Layer w20: v1(733.41,4444.18) 761.03,4444.18 R43.2@765.03,4440.18 Q12.3@927.02,4440.18
  other v1: 733.41,4417.18 733.41,4471.18
NetQ13_3: Q13.3 R44.2 R45.2 | length 161.9
  Top Layer w20: R45.2@765.03,4558.43 Q13.3@926.97,4558.43
  other v1: 733.41,4535.43 733.41,4562.43 733.41,4589.43
NetQ14_3: Q14.3 R73.2 R74.2 | length 161.9
  Top Layer w20: R74.2@765.03,4676.69 Q14.3@926.91,4676.69
  other v1: 733.41,4653.69 733.41,4680.69 733.41,4707.69
NetQ15_3: Q15.3 R75.2 R76.2 | length 161.8
  Top Layer w20: R75.2@765.03,4794.95 Q15.3@926.85,4794.95
  other v1: 733.41,4771.95 733.41,4798.95 733.41,4825.95
NetQ16_3: Q16.3 R77.2 R78.2 | length 161.8
  Top Layer w20: R77.2@765.03,4913.21 Q16.3@926.79,4913.21
  other v1: 733.41,4899.35 733.41,4926.35
NetQ17_1: Q17.1 R93.2 R94.1 | length 170.7
  Top Layer w10: R94.1@1477.71,4563.17 1485.61,4571.07 Q17.1@1538.46,4571.07 1546.24,4578.85 R93.2@1641.91,4578.85
NetQ17_3: Q17.3 R86.2 | length 66.8
  Top Layer w10: R86.2@1638,4461 1639.41,4462.41 Q17.3@1639.41,4527.21
NetQ18_3: Q18.3 R93.1 | length 763.5
  Top Layer w10: R93.1@1704.91,4578.85 1776.41,4507.35 2184.41,4507.35 2252.41,4439.35 Q18.3@2252.41,4281.1
NetQ19_1: Q19.1 R95.2 | length 61.8
  Top Layer w10: R95.2@1863.91,3438.35 1863.91,3432.85 1893.81,3402.94 Q19.1@1893.81,3388.94
NetQ20_3: Q20.3 R123.2 | length 2415
  Top Layer w10: R123.2@911.41,1584.84 1070.91,1744.35 1897.41,1744.35 1949.41,1796.35 1949.41,2985 1897.65,3036.76 Q20.3@1897.65,3064.35
NetQ24_1: Q24.1 Q24.2 Q24.5 Q24.6 R128.2 R129.2 | length 202.9
  Top Layer w20: Q24.2@1805.41,1631.35 Q24.1@1842.81,1631.35 1894.41,1631.35 1899.44,1626.32 R128.2@1899.44,1586.27
  Top Layer w30: Q24.6@1842.15,1528.98 1863.79,1507.35 R129.2@1899.9,1507.35
  other v1: 1937.41,1416.35 1937.41,1441.35 1937.41,1466.35 1937.41,1491.35 1937.41,1516.35 1937.41,1541.35 1937.41,1566.35 1937.41,1591.35 1937.41,1616.35
NetQ28_3: Q28.3 R136.1 | length 67
  Top Layer w18: Q28.3@2454.41,849.95 2517,849.95 2518,848.95 R136.1@2518,846
NetQ29_3: Q29.3 R135.2 | length 112
  Top Layer w18: Q29.3@2339.41,1103.95 2431.01,1103.95 R135.2@2445.41,1118.35
NetQ30_1: Q30.1 R162.1 R174.2 | length 436.1
  Top Layer w20: R174.2@367,3302 359.5,3302 359.5,3333.52 351.01,3342 351.01,3558.74 361.28,3569 361.28,3637.45 Q30.1@359.55,3639.17 369.24,3648.86 369.24,3706.74 372,3709.5 R162.1@372,3717
NetQ30_2: Q30.2 Q30.4 R163.1
NetQ31_1: Q31.1 R161.1 R175.2 | length 242.9
  Bottom Layer w10: Q31.1@159.13,3725.17 156.96,3723 116,3723 107,3732 R175.2@107,3806 107,3813.5 159,3865.5 168,3865.5 173,3870.5 R161.1@173,3878 ; R161.1@174,3888.09 174,3895.59
NetQ31_2: Q31.2 Q31.4 R164.2
NetQ32_1: Q32.1 R167.2 R168.1 | length 81.9
  Top Layer w10: R167.2@164,2399 164,2394 169,2389 R168.1@199.4,2389 ; Q32.1@194.4,2352.24 194.4,2384 R168.1@199.4,2389 ; R168.1@200,2389 R168.1@199.4,2389
NetQ32_3: Q32.3 R169.1 | length 106
  Top Layer w10: Q32.3@157,2257.76 187.26,2257.76 235.5,2306 R169.1@243,2306
NetQ33_1: Q33.1 U7.2 | length 98.4
  Top Layer w10: Q33.1@168.99,2537.6 168.99,2544.98 176.78,2552.77 211.04,2552.77 222.67,2541.14 222.67,2540.73 228.41,2535 U7.2@228.41,2514.21
NetQ33_3: Q33.3 R168.2 | length 79.8
  Top Layer w10: Q33.3@122,2444.76 124.12,2446.88 197.88,2446.88 R168.2@200,2449
NetR62_2: R62.2 R64.2 U1.8 | length 607.9
  Top Layer w10: R62.2@1277.4,4116.32 1328.41,4065.31 1328.41,3917.97 1370.04,3876.35 1494.27,3876.35 1551.22,3819.4 U1.8@1551.22,3777.42
  Bottom Layer w10: R64.2@1277.4,3882.35 1320.4,3925.35 v1(1342.41,3925.35)
NetR63_2: R63.2 R66.2 U1.6 | length 855.9
  Top Layer w10: R63.2@1277.4,4350.35 1360.41,4267.34 1360.41,3972.97 1425.04,3908.35 1507.53,3908.35 1590.59,3825.28 U1.6@1590.59,3777.42
  Bottom Layer w10: R66.2@1277.4,3999.35 1296.4,3980.35 v1(1374.41,3980.35)
NetR65_1: R65.1 R67.2 U1.10 | length 410.7
  Top Layer w10: R65.1@1277.4,3882.36 1315.41,3844.35 1481.02,3844.35 1511.85,3813.51 U1.10@1511.85,3777.42
  Bottom Layer w10: R67.2@1277.4,3765.35 1322.41,3810.35 v1(1322.41,3858.35)
NetR68_1: R68.1 U1.7 | length 625.9
  Top Layer w10: R68.1@1277.4,4233.4 1344.41,4166.39 1344.41,3966.35 1418.41,3892.35 1500.9,3892.35 1570.91,3822.34 U1.7@1570.91,3777.42
NetR69_1: R69.1 U1.11 | length 279.6
  Top Layer w10: R69.1@1277.4,3765.35 1340.4,3828.35 1471.41,3828.35 1492.17,3807.59 U1.11@1492.17,3777.42
NetR70_1: R70.1 U1.9 | length 400
  Top Layer w10: R70.1@1277.4,3999.37 1312.41,3964.37 1312.41,3911.35 1363.41,3860.35 1487.64,3860.35 1531.54,3816.46 U1.9@1531.54,3777.42
NetR71_1: R71.1 S1.1 | length 120.8
  Top Layer w25: S1.1@2635.93,4374.35 2690.91,4319.37 R71.1@2690.91,4276.35
NetR89_2: R89.2 U1.26 | length 969.7
  Top Layer w10: U1.26@1492.17,3444.74 1492.17,3491.1 v1(1508.41,3507.35)
  Bottom Layer w10: v1(1508.41,3507.35) 1496.41,3519.35 1496.41,3624.6 1942.15,4070.35 R89.2@2089.91,4070.35
NetR90_2: R90.2 U1.27 | length 942.3
  Top Layer w10: U1.27@1511.85,3444.74 1511.85,3471.6 1542.41,3502.16 v1(1542.41,3525.35)
  Bottom Layer w10: v1(1542.41,3525.35) 1515.1,3552.66 1515.1,3620.66 1919.78,4025.35 R90.2@2089.91,4025.35
NetR95_1: R95.1 R177.1 U1.37 | length 89
  Top Layer w10: U1.37@1747.09,3502.81 1747.09,3488.28 1767.97,3467.4 1780.47,3454.9 1787.97,3447.4 1797.02,3438.35 R95.1@1800.91,3438.35
NetR99_2: R99.2 U3.8 | length 85.5
  Top Layer w10: U3.8@2475.95,3798.7 2476.85,3799.61 2505.05,3799.61 2518.91,3813.47 2518.91,3835.35 2523.91,3840.35 R99.2@2531.41,3840.35
NetR100_1: R100.1 U4.8 | length 91.6
  Top Layer w10: R100.1@2702.23,3717.35 2755.84,3663.73 U4.8@2771.59,3663.73
NetR101_1: R101.1 U4.4 | length 96.9
  Top Layer w10: R101.1@2575,3580.5 2581.46,3586.96 U4.4@2669.23,3586.96
NetR102_1: R102.1 U4.1 | length 149
  Top Layer w10: R102.1@2538.41,3630.35 2538.41,3637.85 2564.3,3663.73 U4.1@2669.23,3663.73
NetR116_2: R116.2 U5.4 | length 73.8
  Top Layer w20: R116.2@1868.41,4949.35 1925.2,4949.35 1928,4952.14 U5.4@1928,4965.22
NetR117_1: R117.1 U5.7 | length 71.4
  Top Layer w10: R117.1@1995.41,4684.97 2013.6,4703.16 2013.6,4746.06 U5.7@2016.41,4746.06
NetR133_2: R133.2 R134.2 | length 60.1
  Top Layer w20: R134.2@2105.41,3222.85 R133.2@2105.41,3282.98
NetR161_2: R161.2 R178.2 U6.23 | length 151
  Bottom Layer w10: R178.2@77,3925 84.5,3925 97.78,3938.28 104.28,3938.28 ; U6.23@104.28,3992.65 104.28,3938.28 ; R161.2@113,3878 112,3879 112,3930.55 104.28,3938.28
NetR162_2: R162.2 R180.2 U6.22 | length 660.1
  Top Layer w10: v2(109.69,4043) 109.69,3824.68 195.96,3738.41 195.96,3726.93 208.9,3713.98 256.44,3713.98 259.46,3717 R162.2@312,3717
  Bottom Layer w10: R180.2@26,4111 33.5,4111 52,4092.5 52,4080.37 63.37,4069 83.69,4069 v2(109.69,4043) 111.6,4041.09 125.21,4041.09 129.87,4036.43 U6.22@129.87,3992.65
NetR169_2: R169.2 R170.1 | length 37.4
  Top Layer w10: R169.2@242.59,2360.35 242.59,2396.35 R170.1@243.59,2397.35
NetR170_2: R170.2 R171.2 U7.4 | length 103.6
  Top Layer w10: R170.2@243.59,2457.35 244.09,2456.85 R171.2@284.09,2456.85 ; U7.4@279.59,2514.21 279.59,2461.35 R171.2@284.09,2456.85 ; R171.2@287.59,2456.35 284.59,2456.35 R171.2@284.09,2456.85
NetRT6_2: RT6.2 U6.24 | length 490.3
  Bottom Layer w10: U6.24@78.69,3992.65 78.69,3971.98 44,3937.3 44,3587 65.83,3587 97.83,3555 RT6.2@101,3555
NetRT7_1: RT7.1 U7.11 | length 185.4
  Top Layer w10: U7.11@279.59,2746.49 279.59,2725.7 285.32,2719.97 285.32,2719.57 v2(305.18,2699.71)
  Bottom Layer w10: v2(305.18,2699.71) 366.23,2699.71 RT7.1@413.59,2652.35
PACK: D41.1 R140.1 U1.42 | length 464.1
  Top Layer w10: U1.42@1747.09,3601.24 1922.15,3601.24 2000.94,3522.44 D41.1@2000.94,3519.35 2035.41,3484.88 2035.41,3390.85 2038.41,3387.85 R140.1@2038.41,3360.35
PACK+: C61.1 C63.1 D38.2 D40.2 D46.1 Q25.3 Q26.3 Q27.3 Q29.2 R128.1 R129.1 R132.2 R136.2 R138.1 R141.2 R142.2 R143.2 | length 201.9
  Top Layer w20: R128.1@2132.18,1574.53 2132.18,1454.75 2132.18,1447.05 R129.1@2139.88,1454.75
  Top Layer w40: 2655.91,1627.85 C63.1@2655.91,1691.35
  other v1: 2169.69,1416.35 2169.69,1441.35 2169.69,1466.35 2169.69,1491.35 2169.69,1516.35 2169.69,1541.35 2169.69,1566.35 2169.69,1591.35 2169.69,1616.35
PACK-: C62.2 D44.2 D45.2 D46.2 R87.1 R112.2 R113.2 R137.1 R165.1 | length 486.1
  Top Layer w10: R87.1@1375.91,3050.85 1361.41,3036.35 1361.41,2780.35 1377.41,2764.35 1451.41,2764.35
  Bottom Layer w10: R165.1@1365,2929 1365,2879 1377,2867 1423,2867
  other v1: 2240.41,1818.35 2269.41,1818.35 2298.41,1818.35 2327.41,1818.35 1519.41,1820.35 1548.41,1820.35 1577.41,1820.35 1606.41,1820.35 2240.41,1847.35 2269.41,1847.35 2298.41,1847.35 2327.41,1847.35 1519.41,1849.35 1548.41,1849.35 1577.41,1849.35 1606.41,1849.35 2240.41,1876.35 2269.41,1876.35 2298.41,1876.35 2327.41,1876.35 1519.41,1878.35 1548.41,1878.35 1577.41,1878.35 1606.41,1878.35 2240.41,1905.35 2269.41,1905.35 2298.41,1905.35 2327.41,1905.35 1519.41,1907.35 1548.41,1907.35 1577.41,1907.35 1606.41,1907.35 2240.41,1934.35 2269.41,1934.35 2298.41,1934.35 2327.41,1934.35 1519.41,1936.35 1548.41,1936.35 1577.41,1936.35 1606.41,1936.35 2240.41,1963.35 2269.41,1963.35 2298.41,1963.35 2327.41,1963.35 1519.41,1965.35 1548.41,1965.35 1577.41,1965.35 1606.41,1965.35 2240.41,1992.35 2269.41,1992.35 2298.41,1992.35 2327.41,1992.35 1519.41,1994.35 1548.41,1994.35 1577.41,1994.35 1606.41,1994.35 2240.41,2021.35 2269.41,2021.35 2298.41,2021.35 2327.41,2021.35 1519.41,2023.35 1548.41,2023.35 1577.41,2023.35 1606.41,2023.35 2240.41,2050.35 2269.41,2050.35 2298.41,2050.35 2327.41,2050.35 1519.41,2052.35 1548.41,2052.35 1577.41,2052.35 1606.41,2052.35 2240.41,2079.35 2269.41,2079.35 2298.41,2079.35 2327.41,2079.35 1519.41,2081.35 1548.41,2081.35 1577.41,2081.35 1606.41,2081.35 2240.41,2108.35 2269.41,2108.35 2298.41,2108.35 2327.41,2108.35 1519.41,2110.35 1548.41,2110.35 1577.41,2110.35 1606.41,2110.35 2240.41,2137.35 2269.41,2137.35 2298.41,2137.35 2327.41,2137.35 1519.41,2139.35 1548.41,2139.35 1577.41,2139.35 1606.41,2139.35 2240.41,2166.35 2269.41,2166.35 2298.41,2166.35 2327.41,2166.35 1519.41,2168.35 1548.41,2168.35 1577.41,2168.35 1606.41,2168.35 2240.41,2195.35 2269.41,2195.35 2298.41,2195.35 2327.41,2195.35 1519.41,2197.35 1548.41,2197.35 1577.41,2197.35 1606.41,2197.35 2240.41,2224.35 2269.41,2224.35 2298.41,2224.35 2327.41,2224.35 1519.41,2226.35 1548.41,2226.35 1577.41,2226.35 1606.41,2226.35 2240.41,2253.35 2269.41,2253.35 2298.41,2253.35 2327.41,2253.35 1519.41,2255.35 1548.41,2255.35 1577.41,2255.35 1606.41,2255.35 2240.41,2282.35 2269.41,2282.35 2298.41,2282.35 2327.41,2282.35 1519.41,2284.35 1548.41,2284.35 1577.41,2284.35 1606.41,2284.35 2240.41,2311.35 2269.41,2311.35 2298.41,2311.35 2327.41,2311.35 1519.41,2313.35 1548.41,2313.35 1577.41,2313.35 1606.41,2313.35 2240.41,2340.35 2269.41,2340.35 2298.41,2340.35 2327.41,2340.35 1519.41,2342.35 1548.41,2342.35 1577.41,2342.35 1606.41,2342.35 2240.41,2369.35 2269.41,2369.35 2298.41,2369.35 2327.41,2369.35 1519.41,2371.35 1548.41,2371.35 1577.41,2371.35 1606.41,2371.35 2240.41,2398.35 2269.41,2398.35 2298.41,2398.35 2327.41,2398.35 1519.41,2400.35 1548.41,2400.35 1577.41,2400.35 1606.41,2400.35 2240.41,2427.35 2269.41,2427.35 2298.41,2427.35 2327.41,2427.35 1519.41,2429.35 1548.41,2429.35 1577.41,2429.35 1606.41,2429.35 2240.41,2456.35 2269.41,2456.35 2298.41,2456.35 2327.41,2456.35 1519.41,2458.35 1548.41,2458.35 1577.41,2458.35 1606.41,2458.35 2240.41,2485.35 2269.41,2485.35 2298.41,2485.35 2327.41,2485.35 1519.41,2487.35 1548.41,2487.35 1577.41,2487.35 1606.41,2487.35 2240.41,2514.35 2269.41,2514.35 2298.41,2514.35 2327.41,2514.35 1519.41,2516.35 1548.41,2516.35 1577.41,2516.35 1606.41,2516.35 2240.41,2543.35 2269.41,2543.35 2298.41,2543.35 2327.41,2543.35 1519.41,2545.35 1548.41,2545.35 1577.41,2545.35 1606.41,2545.35 2240.41,2572.35 2269.41,2572.35 2298.41,2572.35 2327.41,2572.35 1519.41,2574.35 1548.41,2574.35 1577.41,2574.35 1606.41,2574.35 2240.41,2601.35 2269.41,2601.35 2298.41,2601.35 2327.41,2601.35 1519.41,2603.35 1548.41,2603.35 1577.41,2603.35 1606.41,2603.35 2240.41,2630.35 2269.41,2630.35 2298.41,2630.35 2327.41,2630.35 1519.41,2632.35 1548.41,2632.35 1577.41,2632.35 1606.41,2632.35 2240.41,2659.35 2269.41,2659.35 2298.41,2659.35 2327.41,2659.35 1519.41,2661.35 1548.41,2661.35 1577.41,2661.35 1606.41,2661.35 2240.41,2688.35 2269.41,2688.35 2298.41,2688.35 2327.41,2688.35 1519.41,2690.35 1548.41,2690.35 1577.41,2690.35 1606.41,2690.35 2240.41,2717.35 2269.41,2717.35 2298.41,2717.35 2327.41,2717.35 1519.41,2719.35 1548.41,2719.35 1577.41,2719.35 1606.41,2719.35 2240.41,2746.35 2269.41,2746.35 2298.41,2746.35 2327.41,2746.35 1519.41,2748.35 1548.41,2748.35 1577.41,2748.35 1606.41,2748.35 2240.41,2775.35 2269.41,2775.35 2298.41,2775.35 2327.41,2775.35 1519.41,2777.35 1548.41,2777.35 1577.41,2777.35 1606.41,2777.35 2240.41,2804.35 2269.41,2804.35 2298.41,2804.35 2327.41,2804.35 1519.41,2806.35 1548.41,2806.35 1577.41,2806.35 1606.41,2806.35 2240.41,2833.35 2269.41,2833.35 2298.41,2833.35 2327.41,2833.35 1519.41,2835.35 1548.41,2835.35 1577.41,2835.35 1606.41,2835.35 2240.41,2862.35 2269.41,2862.35 2298.41,2862.35 2327.41,2862.35 1519.41,2864.35 1548.41,2864.35 1577.41,2864.35 1606.41,2864.35 2240.41,2891.35 2269.41,2891.35 2298.41,2891.35 2327.41,2891.35 1519.41,2893.35 1548.41,2893.35 1577.41,2893.35 1606.41,2893.35 2240.41,2920.35 2269.41,2920.35 2298.41,2920.35 2327.41,2920.35 1519.41,2922.35 1548.41,2922.35 1577.41,2922.35 1606.41,2922.35
PDSG: D32.1 R126.1 U1.39 | length 531.9
  Top Layer w10: U1.39@1747.09,3542.18 1809.2,3542.18 1863.04,3488.35 1893.41,3488.35 1932.62,3449.13 1932.62,3234.6 D32.1@1946.88,3220.35
  Top Layer w20: D32.1@1946.88,3220.35 1946.88,3153.59 R126.1@1951.41,3149.06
